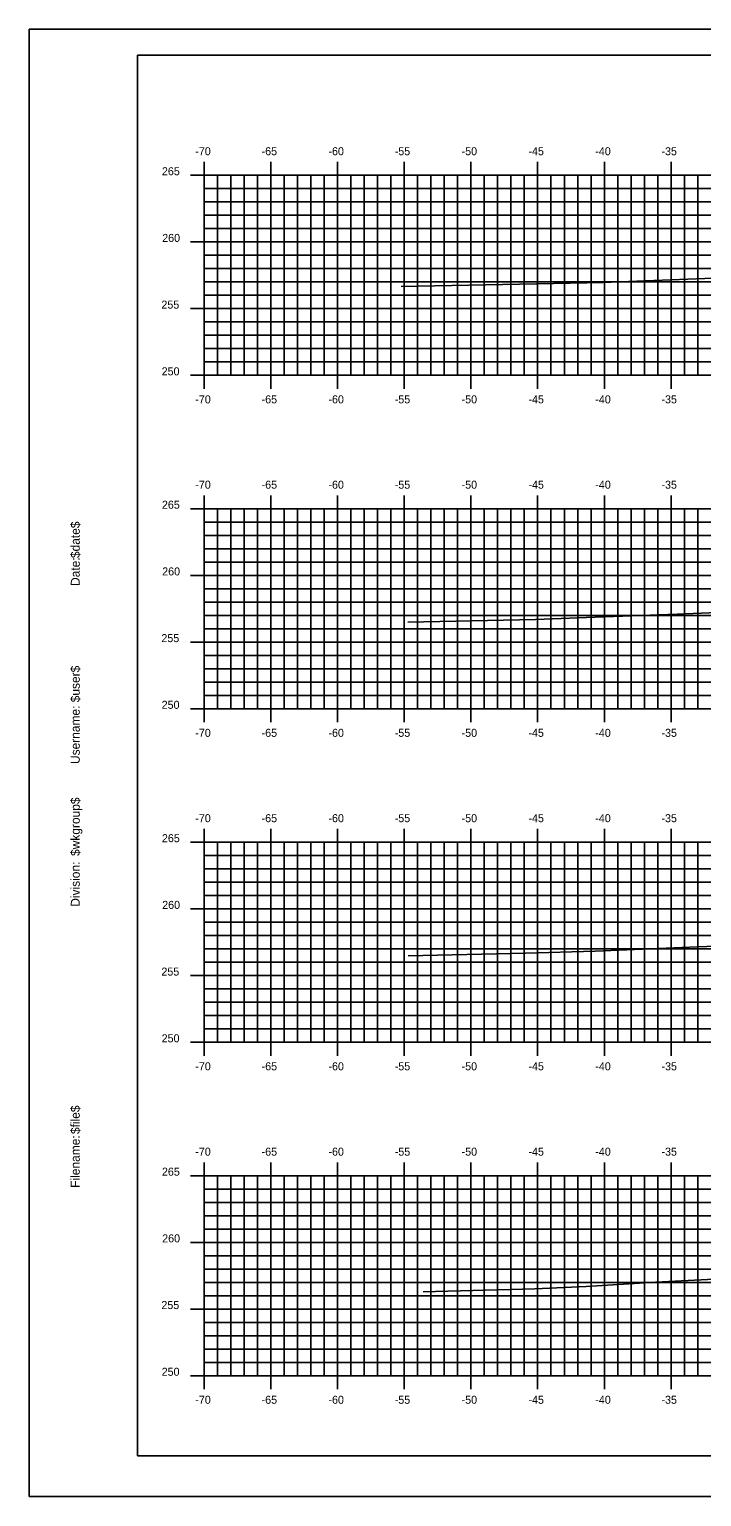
# Model space of a CAD drawing. Extents: x 856680 to 856850, y 366268 to 366378.
# Drawn here: x 856680 to 856730.4, y 366268.2 to 366378.2 of the extents above; entities that cross this region are included whole.
import ezdxf

# ---------------------------------------------------------------- set-up
doc = ezdxf.new("R2010")
doc.units = 0
for name, color, linetype in [('BORDER', 7, 'Continuous'), ('H_V ANNOTATION', 7, 'Continuous'), ('MAJOR', 7, 'Continuous'), ('MINOR', 7, 'Continuous'), ('PLOT BOUNDARY', 7, 'Continuous'), ('S_Roadway_Centerline', 7, 'Continuous')]:
    doc.layers.add(name, color=color, linetype=linetype)

msp = doc.modelspace()

# ---------------------------------------------------------------- linework, layer by layer
at = {"layer": 'BORDER'}
for p, q in [((856848.12, 366376.24), (856688.12, 366376.24)), ((856688.12, 366376.24), (856688.12, 366271.24)), ((856688.12, 366271.24), (856848.12, 366271.24))]:
    msp.add_line(p, q, dxfattribs=at)
at = {"layer": 'MAJOR'}
for p, q in [((856693.12, 366368.24), (856693.12, 366367.24)), ((856698.12, 366368.24), (856698.12, 366367.24)), ((856703.12, 366368.24), (856703.12, 366367.24)), ((856708.12, 366368.24), (856708.12, 366367.24)), ((856713.12, 366368.24), (856713.12, 366367.24)), ((856718.12, 366368.24), (856718.12, 366367.24)), ((856723.12, 366368.24), (856723.12, 366367.24)), ((856728.12, 366368.24), (856728.12, 366367.24)), ((856692.11, 366367.24), (856693.12, 366367.24)), ((856693.12, 366367.24), (856833.12, 366367.24)), ((856693.12, 366352.24), (856693.12, 366367.24)), ((856693.12, 366352.24), (856693.12, 366367.24)), ((856693.12, 366367.24), (856833.12, 366367.24)), ((856698.12, 366352.24), (856698.12, 366367.24)), ((856703.12, 366352.24), (856703.12, 366367.24)), ((856708.12, 366352.24), (856708.12, 366367.24)), ((856713.12, 366352.24), (856713.12, 366367.24)), ((856718.12, 366352.24), (856718.12, 366367.24)), ((856723.12, 366352.24), (856723.12, 366367.24)), ((856728.12, 366352.24), (856728.12, 366367.24)), ((856692.11, 366362.24), (856693.12, 366362.24)), ((856693.12, 366362.24), (856833.12, 366362.24)), ((856692.11, 366357.24), (856693.12, 366357.24)), ((856693.12, 366357.24), (856833.12, 366357.24)), ((856692.11, 366352.24), (856693.12, 366352.24)), ((856693.12, 366352.24), (856833.12, 366352.24)), ((856693.12, 366352.24), (856833.12, 366352.24)), ((856693.12, 366351.23), (856693.12, 366352.24)), ((856698.12, 366351.23), (856698.12, 366352.24)), ((856703.12, 366351.23), (856703.12, 366352.24)), ((856708.12, 366351.23), (856708.12, 366352.24)), ((856713.12, 366351.23), (856713.12, 366352.24)), ((856718.12, 366351.23), (856718.12, 366352.24)), ((856723.12, 366351.23), (856723.12, 366352.24)), ((856728.12, 366351.23), (856728.12, 366352.24)), ((856693.12, 366343.24), (856693.12, 366342.24)), ((856698.12, 366343.24), (856698.12, 366342.24)), ((856703.12, 366343.24), (856703.12, 366342.24)), ((856708.12, 366343.24), (856708.12, 366342.24)), ((856713.12, 366343.24), (856713.12, 366342.24)), ((856718.12, 366343.24), (856718.12, 366342.24)), ((856723.12, 366343.24), (856723.12, 366342.24)), ((856728.12, 366343.24), (856728.12, 366342.24)), ((856692.11, 366342.24), (856693.12, 366342.24)), ((856693.12, 366342.24), (856833.12, 366342.24)), ((856693.12, 366327.24), (856693.12, 366342.24)), ((856693.12, 366327.24), (856693.12, 366342.24)), ((856693.12, 366342.24), (856833.12, 366342.24)), ((856698.12, 366327.24), (856698.12, 366342.24)), ((856703.12, 366327.24), (856703.12, 366342.24)), ((856708.12, 366327.24), (856708.12, 366342.24)), ((856713.12, 366327.24), (856713.12, 366342.24)), ((856718.12, 366327.24), (856718.12, 366342.24)), ((856723.12, 366327.24), (856723.12, 366342.24)), ((856728.12, 366327.24), (856728.12, 366342.24)), ((856692.11, 366337.24), (856693.12, 366337.24)), ((856693.12, 366337.24), (856833.12, 366337.24)), ((856692.11, 366332.24), (856693.12, 366332.24)), ((856693.12, 366332.24), (856833.12, 366332.24)), ((856692.11, 366327.24), (856693.12, 366327.24)), ((856693.12, 366327.24), (856833.12, 366327.24)), ((856693.12, 366327.24), (856833.12, 366327.24)), ((856693.12, 366326.23), (856693.12, 366327.24)), ((856698.12, 366326.23), (856698.12, 366327.24)), ((856703.12, 366326.23), (856703.12, 366327.24)), ((856708.12, 366326.23), (856708.12, 366327.24)), ((856713.12, 366326.23), (856713.12, 366327.24)), ((856718.12, 366326.23), (856718.12, 366327.24)), ((856723.12, 366326.23), (856723.12, 366327.24)), ((856728.12, 366326.23), (856728.12, 366327.24)), ((856693.12, 366318.24), (856693.12, 366317.24)), ((856698.12, 366318.24), (856698.12, 366317.24)), ((856703.12, 366318.24), (856703.12, 366317.24)), ((856708.12, 366318.24), (856708.12, 366317.24)), ((856713.12, 366318.24), (856713.12, 366317.24)), ((856718.12, 366318.24), (856718.12, 366317.24)), ((856723.12, 366318.24), (856723.12, 366317.24)), ((856728.12, 366318.24), (856728.12, 366317.24)), ((856692.11, 366317.24), (856693.12, 366317.24)), ((856693.12, 366317.24), (856833.12, 366317.24)), ((856693.12, 366302.24), (856693.12, 366317.24)), ((856693.12, 366302.24), (856693.12, 366317.24)), ((856693.12, 366317.24), (856833.12, 366317.24)), ((856698.12, 366302.24), (856698.12, 366317.24)), ((856703.12, 366302.24), (856703.12, 366317.24)), ((856708.12, 366302.24), (856708.12, 366317.24)), ((856713.12, 366302.24), (856713.12, 366317.24)), ((856718.12, 366302.24), (856718.12, 366317.24)), ((856723.12, 366302.24), (856723.12, 366317.24)), ((856728.12, 366302.24), (856728.12, 366317.24)), ((856692.11, 366312.24), (856693.12, 366312.24)), ((856693.12, 366312.24), (856833.12, 366312.24)), ((856692.11, 366307.24), (856693.12, 366307.24)), ((856693.12, 366307.24), (856833.12, 366307.24)), ((856692.11, 366302.24), (856693.12, 366302.24)), ((856693.12, 366302.24), (856833.12, 366302.24)), ((856693.12, 366302.24), (856833.12, 366302.24)), ((856693.12, 366301.23), (856693.12, 366302.24)), ((856698.12, 366301.23), (856698.12, 366302.24)), ((856703.12, 366301.23), (856703.12, 366302.24)), ((856708.12, 366301.23), (856708.12, 366302.24)), ((856713.12, 366301.23), (856713.12, 366302.24)), ((856718.12, 366301.23), (856718.12, 366302.24)), ((856723.12, 366301.23), (856723.12, 366302.24)), ((856728.12, 366301.23), (856728.12, 366302.24)), ((856693.12, 366293.24), (856693.12, 366292.24)), ((856698.12, 366293.24), (856698.12, 366292.24)), ((856703.12, 366293.24), (856703.12, 366292.24)), ((856708.12, 366293.24), (856708.12, 366292.24)), ((856713.12, 366293.24), (856713.12, 366292.24)), ((856718.12, 366293.24), (856718.12, 366292.24)), ((856723.12, 366293.24), (856723.12, 366292.24)), ((856728.12, 366293.24), (856728.12, 366292.24)), ((856692.11, 366292.24), (856693.12, 366292.24)), ((856693.12, 366292.24), (856833.12, 366292.24)), ((856693.12, 366277.24), (856693.12, 366292.24)), ((856693.12, 366277.24), (856693.12, 366292.24)), ((856693.12, 366292.24), (856833.12, 366292.24)), ((856698.12, 366277.24), (856698.12, 366292.24)), ((856703.12, 366277.24), (856703.12, 366292.24)), ((856708.12, 366277.24), (856708.12, 366292.24)), ((856713.12, 366277.24), (856713.12, 366292.24)), ((856718.12, 366277.24), (856718.12, 366292.24)), ((856723.12, 366277.24), (856723.12, 366292.24)), ((856728.12, 366277.24), (856728.12, 366292.24)), ((856692.11, 366287.24), (856693.12, 366287.24)), ((856693.12, 366287.24), (856833.12, 366287.24)), ((856692.11, 366282.24), (856693.12, 366282.24)), ((856693.12, 366282.24), (856833.12, 366282.24)), ((856692.11, 366277.24), (856693.12, 366277.24)), ((856693.12, 366277.24), (856833.12, 366277.24)), ((856693.12, 366277.24), (856833.12, 366277.24)), ((856693.12, 366276.23), (856693.12, 366277.24)), ((856698.12, 366276.23), (856698.12, 366277.24)), ((856703.12, 366276.23), (856703.12, 366277.24)), ((856708.12, 366276.23), (856708.12, 366277.24)), ((856713.12, 366276.23), (856713.12, 366277.24)), ((856718.12, 366276.23), (856718.12, 366277.24)), ((856723.12, 366276.23), (856723.12, 366277.24)), ((856728.12, 366276.23), (856728.12, 366277.24))]:
    msp.add_line(p, q, dxfattribs=at)
at = {"layer": 'MINOR'}
for p, q in [((856694.12, 366352.24), (856694.12, 366367.24)), ((856695.12, 366352.24), (856695.12, 366367.24)), ((856696.12, 366352.24), (856696.12, 366367.24)), ((856697.12, 366352.24), (856697.12, 366367.24)), ((856699.12, 366352.24), (856699.12, 366367.24)), ((856700.12, 366352.24), (856700.12, 366367.24)), ((856701.12, 366352.24), (856701.12, 366367.24)), ((856702.12, 366352.24), (856702.12, 366367.24)), ((856704.12, 366352.24), (856704.12, 366367.24)), ((856705.12, 366352.24), (856705.12, 366367.24)), ((856706.12, 366352.24), (856706.12, 366367.24)), ((856707.12, 366352.24), (856707.12, 366367.24)), ((856709.12, 366352.24), (856709.12, 366367.24)), ((856710.12, 366352.24), (856710.12, 366367.24)), ((856711.12, 366352.24), (856711.12, 366367.24)), ((856712.12, 366352.24), (856712.12, 366367.24)), ((856714.12, 366352.24), (856714.12, 366367.24)), ((856715.12, 366352.24), (856715.12, 366367.24)), ((856716.12, 366352.24), (856716.12, 366367.24)), ((856717.12, 366352.24), (856717.12, 366367.24)), ((856719.12, 366352.24), (856719.12, 366367.24)), ((856720.12, 366352.24), (856720.12, 366367.24)), ((856721.12, 366352.24), (856721.12, 366367.24)), ((856722.12, 366352.24), (856722.12, 366367.24)), ((856724.12, 366352.24), (856724.12, 366367.24)), ((856725.12, 366352.24), (856725.12, 366367.24)), ((856726.12, 366352.24), (856726.12, 366367.24)), ((856727.12, 366352.24), (856727.12, 366367.24)), ((856729.12, 366352.24), (856729.12, 366367.24)), ((856730.12, 366352.24), (856730.12, 366367.24)), ((856693.12, 366366.24), (856833.12, 366366.24)), ((856693.12, 366366.24), (856694.12, 366366.24)), ((856693.12, 366365.24), (856833.12, 366365.24)), ((856693.12, 366365.24), (856694.12, 366365.24)), ((856693.12, 366364.24), (856833.12, 366364.24)), ((856693.12, 366364.24), (856694.12, 366364.24)), ((856693.12, 366363.24), (856833.12, 366363.24)), ((856693.12, 366363.24), (856694.12, 366363.24)), ((856693.12, 366361.24), (856833.12, 366361.24)), ((856693.12, 366361.24), (856694.12, 366361.24)), ((856693.12, 366360.24), (856833.12, 366360.24)), ((856693.12, 366360.24), (856694.12, 366360.24)), ((856693.12, 366359.24), (856833.12, 366359.24)), ((856693.12, 366359.24), (856694.12, 366359.24)), ((856693.12, 366358.24), (856833.12, 366358.24)), ((856693.12, 366358.24), (856694.12, 366358.24)), ((856693.12, 366356.24), (856833.12, 366356.24)), ((856693.12, 366356.24), (856694.12, 366356.24)), ((856693.12, 366355.24), (856833.12, 366355.24)), ((856693.12, 366355.24), (856694.12, 366355.24)), ((856693.12, 366354.24), (856833.12, 366354.24)), ((856693.12, 366354.24), (856694.12, 366354.24)), ((856693.12, 366353.24), (856833.12, 366353.24)), ((856693.12, 366353.24), (856694.12, 366353.24)), ((856694.12, 366327.24), (856694.12, 366342.24)), ((856695.12, 366327.24), (856695.12, 366342.24)), ((856696.12, 366327.24), (856696.12, 366342.24)), ((856697.12, 366327.24), (856697.12, 366342.24)), ((856699.12, 366327.24), (856699.12, 366342.24)), ((856700.12, 366327.24), (856700.12, 366342.24)), ((856701.12, 366327.24), (856701.12, 366342.24)), ((856702.12, 366327.24), (856702.12, 366342.24)), ((856704.12, 366327.24), (856704.12, 366342.24)), ((856705.12, 366327.24), (856705.12, 366342.24)), ((856706.12, 366327.24), (856706.12, 366342.24)), ((856707.12, 366327.24), (856707.12, 366342.24)), ((856709.12, 366327.24), (856709.12, 366342.24)), ((856710.12, 366327.24), (856710.12, 366342.24)), ((856711.12, 366327.24), (856711.12, 366342.24)), ((856712.12, 366327.24), (856712.12, 366342.24)), ((856714.12, 366327.24), (856714.12, 366342.24)), ((856715.12, 366327.24), (856715.12, 366342.24)), ((856716.12, 366327.24), (856716.12, 366342.24)), ((856717.12, 366327.24), (856717.12, 366342.24)), ((856719.12, 366327.24), (856719.12, 366342.24)), ((856720.12, 366327.24), (856720.12, 366342.24)), ((856721.12, 366327.24), (856721.12, 366342.24)), ((856722.12, 366327.24), (856722.12, 366342.24)), ((856724.12, 366327.24), (856724.12, 366342.24)), ((856725.12, 366327.24), (856725.12, 366342.24)), ((856726.12, 366327.24), (856726.12, 366342.24)), ((856727.12, 366327.24), (856727.12, 366342.24)), ((856729.12, 366327.24), (856729.12, 366342.24)), ((856730.12, 366327.24), (856730.12, 366342.24)), ((856693.12, 366341.24), (856833.12, 366341.24)), ((856693.12, 366341.24), (856694.12, 366341.24)), ((856693.12, 366340.24), (856833.12, 366340.24)), ((856693.12, 366340.24), (856694.12, 366340.24)), ((856693.12, 366339.24), (856833.12, 366339.24)), ((856693.12, 366339.24), (856694.12, 366339.24)), ((856693.12, 366338.24), (856833.12, 366338.24)), ((856693.12, 366338.24), (856694.12, 366338.24)), ((856693.12, 366336.24), (856833.12, 366336.24)), ((856693.12, 366336.24), (856694.12, 366336.24)), ((856693.12, 366335.24), (856833.12, 366335.24)), ((856693.12, 366335.24), (856694.12, 366335.24)), ((856693.12, 366334.24), (856833.12, 366334.24)), ((856693.12, 366334.24), (856694.12, 366334.24)), ((856693.12, 366333.24), (856833.12, 366333.24)), ((856693.12, 366333.24), (856694.12, 366333.24)), ((856693.12, 366331.24), (856833.12, 366331.24)), ((856693.12, 366331.24), (856694.12, 366331.24)), ((856693.12, 366330.24), (856833.12, 366330.24)), ((856693.12, 366330.24), (856694.12, 366330.24)), ((856693.12, 366329.24), (856833.12, 366329.24)), ((856693.12, 366329.24), (856694.12, 366329.24)), ((856693.12, 366328.24), (856833.12, 366328.24)), ((856693.12, 366328.24), (856694.12, 366328.24)), ((856694.12, 366302.24), (856694.12, 366317.24)), ((856695.12, 366302.24), (856695.12, 366317.24)), ((856696.12, 366302.24), (856696.12, 366317.24)), ((856697.12, 366302.24), (856697.12, 366317.24)), ((856699.12, 366302.24), (856699.12, 366317.24)), ((856700.12, 366302.24), (856700.12, 366317.24)), ((856701.12, 366302.24), (856701.12, 366317.24)), ((856702.12, 366302.24), (856702.12, 366317.24)), ((856704.12, 366302.24), (856704.12, 366317.24)), ((856705.12, 366302.24), (856705.12, 366317.24)), ((856706.12, 366302.24), (856706.12, 366317.24)), ((856707.12, 366302.24), (856707.12, 366317.24)), ((856709.12, 366302.24), (856709.12, 366317.24)), ((856710.12, 366302.24), (856710.12, 366317.24)), ((856711.12, 366302.24), (856711.12, 366317.24)), ((856712.12, 366302.24), (856712.12, 366317.24)), ((856714.12, 366302.24), (856714.12, 366317.24)), ((856715.12, 366302.24), (856715.12, 366317.24)), ((856716.12, 366302.24), (856716.12, 366317.24)), ((856717.12, 366302.24), (856717.12, 366317.24)), ((856719.12, 366302.24), (856719.12, 366317.24)), ((856720.12, 366302.24), (856720.12, 366317.24)), ((856721.12, 366302.24), (856721.12, 366317.24)), ((856722.12, 366302.24), (856722.12, 366317.24)), ((856724.12, 366302.24), (856724.12, 366317.24)), ((856725.12, 366302.24), (856725.12, 366317.24)), ((856726.12, 366302.24), (856726.12, 366317.24)), ((856727.12, 366302.24), (856727.12, 366317.24)), ((856729.12, 366302.24), (856729.12, 366317.24)), ((856730.12, 366302.24), (856730.12, 366317.24)), ((856693.12, 366316.24), (856833.12, 366316.24)), ((856693.12, 366316.24), (856694.12, 366316.24)), ((856693.12, 366315.24), (856833.12, 366315.24)), ((856693.12, 366315.24), (856694.12, 366315.24)), ((856693.12, 366314.24), (856833.12, 366314.24)), ((856693.12, 366314.24), (856694.12, 366314.24)), ((856693.12, 366313.24), (856833.12, 366313.24)), ((856693.12, 366313.24), (856694.12, 366313.24)), ((856693.12, 366311.24), (856833.12, 366311.24)), ((856693.12, 366311.24), (856694.12, 366311.24)), ((856693.12, 366310.24), (856833.12, 366310.24)), ((856693.12, 366310.24), (856694.12, 366310.24)), ((856693.12, 366309.24), (856833.12, 366309.24)), ((856693.12, 366309.24), (856694.12, 366309.24)), ((856693.12, 366308.24), (856833.12, 366308.24)), ((856693.12, 366308.24), (856694.12, 366308.24)), ((856693.12, 366306.24), (856833.12, 366306.24)), ((856693.12, 366306.24), (856694.12, 366306.24)), ((856693.12, 366305.24), (856833.12, 366305.24)), ((856693.12, 366305.24), (856694.12, 366305.24)), ((856693.12, 366304.24), (856833.12, 366304.24)), ((856693.12, 366304.24), (856694.12, 366304.24)), ((856693.12, 366303.24), (856833.12, 366303.24)), ((856693.12, 366303.24), (856694.12, 366303.24)), ((856693.12, 366291.24), (856833.12, 366291.24)), ((856693.12, 366291.24), (856694.12, 366291.24)), ((856694.12, 366277.24), (856694.12, 366292.24)), ((856695.12, 366277.24), (856695.12, 366292.24)), ((856696.12, 366277.24), (856696.12, 366292.24)), ((856697.12, 366277.24), (856697.12, 366292.24)), ((856699.12, 366277.24), (856699.12, 366292.24)), ((856700.12, 366277.24), (856700.12, 366292.24)), ((856701.12, 366277.24), (856701.12, 366292.24)), ((856702.12, 366277.24), (856702.12, 366292.24)), ((856704.12, 366277.24), (856704.12, 366292.24)), ((856705.12, 366277.24), (856705.12, 366292.24)), ((856706.12, 366277.24), (856706.12, 366292.24)), ((856707.12, 366277.24), (856707.12, 366292.24)), ((856709.12, 366277.24), (856709.12, 366292.24)), ((856710.12, 366277.24), (856710.12, 366292.24)), ((856711.12, 366277.24), (856711.12, 366292.24)), ((856712.12, 366277.24), (856712.12, 366292.24)), ((856714.12, 366277.24), (856714.12, 366292.24)), ((856715.12, 366277.24), (856715.12, 366292.24)), ((856716.12, 366277.24), (856716.12, 366292.24)), ((856717.12, 366277.24), (856717.12, 366292.24)), ((856719.12, 366277.24), (856719.12, 366292.24)), ((856720.12, 366277.24), (856720.12, 366292.24)), ((856721.12, 366277.24), (856721.12, 366292.24)), ((856722.12, 366277.24), (856722.12, 366292.24)), ((856724.12, 366277.24), (856724.12, 366292.24)), ((856725.12, 366277.24), (856725.12, 366292.24)), ((856726.12, 366277.24), (856726.12, 366292.24)), ((856727.12, 366277.24), (856727.12, 366292.24)), ((856729.12, 366277.24), (856729.12, 366292.24)), ((856730.12, 366277.24), (856730.12, 366292.24)), ((856693.12, 366290.24), (856833.12, 366290.24)), ((856693.12, 366290.24), (856694.12, 366290.24)), ((856693.12, 366289.24), (856833.12, 366289.24)), ((856693.12, 366289.24), (856694.12, 366289.24)), ((856693.12, 366288.24), (856833.12, 366288.24)), ((856693.12, 366288.24), (856694.12, 366288.24)), ((856693.12, 366286.24), (856833.12, 366286.24)), ((856693.12, 366286.24), (856694.12, 366286.24)), ((856693.12, 366285.24), (856833.12, 366285.24)), ((856693.12, 366285.24), (856694.12, 366285.24)), ((856693.12, 366284.24), (856833.12, 366284.24)), ((856693.12, 366284.24), (856694.12, 366284.24)), ((856693.12, 366283.24), (856833.12, 366283.24)), ((856693.12, 366283.24), (856694.12, 366283.24)), ((856693.12, 366281.24), (856833.12, 366281.24)), ((856693.12, 366281.24), (856694.12, 366281.24)), ((856693.12, 366280.24), (856833.12, 366280.24)), ((856693.12, 366280.24), (856694.12, 366280.24)), ((856693.12, 366279.24), (856833.12, 366279.24)), ((856693.12, 366279.24), (856694.12, 366279.24)), ((856693.12, 366278.24), (856833.12, 366278.24)), ((856693.12, 366278.24), (856694.12, 366278.24))]:
    msp.add_line(p, q, dxfattribs=at)
at = {"layer": 'PLOT BOUNDARY'}
msp.add_lwpolyline([(856680.02, 366268.18), (856850.02, 366268.18), (856850.02, 366378.18), (856680.02, 366378.18)], close=True, dxfattribs=at)
at = {"layer": 'S_Roadway_Centerline'}
for points in [[(856707.88, 366358.9), (856721.83, 366359.17), (856722.6, 366359.19), (856723, 366359.19), (856738.29, 366359.79)], [(856708.4, 366333.74), (856717.95, 366333.94), (856722.44, 366334.1), (856728.58, 366334.34), (856738.85, 366334.76)], [(856708.42, 366308.72), (856717.22, 366308.91), (856722.42, 366309.08), (856729.52, 366309.36), (856739.02, 366309.75)], [(856709.55, 366283.54), (856717.9, 366283.76), (856721.76, 366283.94), (856726.96, 366284.25), (856740.12, 366284.93)]]:
    msp.add_lwpolyline(points, dxfattribs=at)

# ---------------------------------------------------------------- texts
at = {"layer": 'BORDER'}
for s, p in [('$date$', (856683.8, 366338.54)), ('Date:', (856683.8, 366336.45)), ('$user$', (856683.8, 366327.73)), ('Username:', (856683.8, 366323.1)), ('$wkgroup$', (856683.8, 366316.21)), ('Division:', (856683.8, 366312.4)), ('$file$', (856683.8, 366295.36)), ('Filename:', (856683.8, 366291.33))]:
    msp.add_text(s, height=0.67, rotation=90, dxfattribs=at).set_placement(p)
at = {"layer": 'H_V ANNOTATION'}
for s, p in [('-70', (856692.46, 366368.74)), ('-65', (856697.43, 366368.74)), ('-60', (856702.44, 366368.74)), ('-55', (856707.41, 366368.74)), ('-50', (856712.42, 366368.74)), ('-45', (856717.43, 366368.74)), ('-40', (856722.44, 366368.74)), ('-35', (856727.4, 366368.74)), ('265', (856689.96, 366367.24)), ('260', (856689.98, 366362.24)), ('255', (856689.92, 366357.24)), ('250', (856689.94, 366352.24)), ('-70', (856692.46, 366350.14)), ('-65', (856697.43, 366350.14)), ('-60', (856702.44, 366350.14)), ('-55', (856707.41, 366350.14)), ('-50', (856712.42, 366350.14)), ('-45', (856717.43, 366350.14)), ('-40', (856722.44, 366350.14)), ('-35', (856727.4, 366350.14)), ('-70', (856692.46, 366343.74)), ('-65', (856697.43, 366343.74)), ('-60', (856702.44, 366343.74)), ('-55', (856707.41, 366343.74)), ('-50', (856712.42, 366343.74)), ('-45', (856717.43, 366343.74)), ('-40', (856722.44, 366343.74)), ('-35', (856727.4, 366343.74)), ('265', (856689.96, 366342.24)), ('260', (856689.98, 366337.24)), ('255', (856689.92, 366332.24)), ('250', (856689.94, 366327.24)), ('-70', (856692.46, 366325.14)), ('-65', (856697.43, 366325.14)), ('-60', (856702.44, 366325.14)), ('-55', (856707.41, 366325.14)), ('-50', (856712.42, 366325.14)), ('-45', (856717.43, 366325.14)), ('-40', (856722.44, 366325.14)), ('-35', (856727.4, 366325.14)), ('-70', (856692.46, 366318.74)), ('-65', (856697.43, 366318.74)), ('-60', (856702.44, 366318.74)), ('-55', (856707.41, 366318.74)), ('-50', (856712.42, 366318.74)), ('-45', (856717.43, 366318.74)), ('-40', (856722.44, 366318.74)), ('-35', (856727.4, 366318.74)), ('265', (856689.96, 366317.24)), ('260', (856689.98, 366312.24)), ('255', (856689.92, 366307.24)), ('250', (856689.94, 366302.24)), ('-70', (856692.46, 366300.14)), ('-65', (856697.43, 366300.14)), ('-60', (856702.44, 366300.14)), ('-55', (856707.41, 366300.14)), ('-50', (856712.42, 366300.14)), ('-45', (856717.43, 366300.14)), ('-40', (856722.44, 366300.14)), ('-35', (856727.4, 366300.14)), ('-70', (856692.46, 366293.74)), ('-65', (856697.43, 366293.74)), ('-60', (856702.44, 366293.74)), ('-55', (856707.41, 366293.74)), ('-50', (856712.42, 366293.74)), ('-45', (856717.43, 366293.74)), ('-40', (856722.44, 366293.74)), ('-35', (856727.4, 366293.74)), ('265', (856689.96, 366292.24)), ('260', (856689.98, 366287.24)), ('255', (856689.92, 366282.24)), ('250', (856689.94, 366277.24)), ('-70', (856692.46, 366275.14)), ('-65', (856697.43, 366275.14)), ('-60', (856702.44, 366275.14)), ('-55', (856707.41, 366275.14)), ('-50', (856712.42, 366275.14)), ('-45', (856717.43, 366275.14)), ('-40', (856722.44, 366275.14)), ('-35', (856727.4, 366275.14))]:
    msp.add_text(s, height=0.6, dxfattribs=at).set_placement(p)

doc.saveas('drawing.dxf')
